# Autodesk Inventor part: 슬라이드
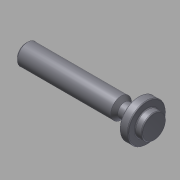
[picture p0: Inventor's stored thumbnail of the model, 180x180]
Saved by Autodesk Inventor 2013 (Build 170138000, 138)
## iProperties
Company: 한국ATC센터
Created: 2015-12
Part Number: 슬라이드
Document SubType Name: Modeling
Designer: mdu
Density: 7.86 g/cm^3
Mass: 72.8967 g
Surface Area: 36.3054 cm^2
Volume: 9.27439 cm^3
Material: 강철, 연강
Author: mdu
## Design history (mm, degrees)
sketch "스케치1"
  geometry: L1 (-35, 0)-(35, 0); L2 (35, 0)-(35, 11); L3 (35, 11)-(30, 11); L4 (30, 11)-(30, 4); L5 (30, 4)-(22, 4); L6 (22, 4)-(20, 6); L7 (20, 6)-(-35, 6); L8 (-35, 6)-(-35, 0); 1 further point
  constraints: 16 end point, 4 parallel, 2 midpoint, 2 perpendicular, 1 horizontal
  dimensions: "d0" = 70 distance of L1.start L1.end; "d1" = 12 diameter of L7 L1; "d2" = 22 diameter of L3 L1; "d3" = 5 distance of L2.end L3.end; "d4" = 8 diameter of L5 L1; "d5" = 135 deg angle of L6 L5; "d6" = 15 distance from line of L2 L6.end
revolve "회전1" sketch "스케치1" stored, may be unused: angle "d7" = 90 deg
chamfer "모따기1" distance "d8" = 1; stored, may be unused: second distance "d9" = 2, angle "d10" = 45 deg
fillet "모깎기1" dims "d11" = 0.5
sketch "스케치5"
  geometry: C1 r 7 at (0, 0); 1 further point
  constraints: 1 centre point, 1 coincident
  dimensions: "d23" = 14 diameter of C1
extrude "돌출2" join sketch "스케치5" distance "d24" = 4; taper "d25" = 0 deg
fillet "모깎기3" dims "d26" = 0.5
node "솔리드1"
